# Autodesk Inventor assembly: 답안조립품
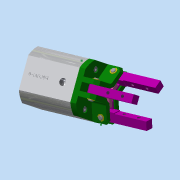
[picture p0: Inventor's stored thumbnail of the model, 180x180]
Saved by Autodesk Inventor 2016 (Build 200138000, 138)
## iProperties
Created: 2020-02
Part Number: 답안조립품
Document SubType Name: Assembly
Designer: MIRAE
Author: MIRAE
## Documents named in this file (11)
- C:\Users\MIRAE\Desktop\700206V1026\답안조립품.iam
- C:\Users\MIRAE\Desktop\700206V1026\본체.ipt
- C:\Users\MIRAE\Desktop\700206V1026\본체헤드.ipt
- C:\Users\MIRAE\Desktop\700206V1026\로드.ipt
- C:\Users\MIRAE\Desktop\700206V1026\핑거.ipt
- C:\Users\MIRAE\Desktop\700206V1026\핀 A.ipt
- C:\Users\MIRAE\Desktop\700206V1026\E링.ipt
- C:\Users\MIRAE\Desktop\700206V1026\볼트 M4.ipt
- C:\Users\MIRAE\Desktop\700206V1026\피스톤.ipt
- C:\Users\MIRAE\Desktop\700206V1026\O-RING 34x40.ipt
- C:\Users\MIRAE\Desktop\700206V1026\O-RING 12x16.ipt
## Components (16 placed, 6 different names)
1. 핑거:3
2. 핑거:4
3. 핑거:5
4. 핀 A:1
5. E링:1
6. E링:2
7. 핀 A:2
8. E링:3
9. E링:4
10. 핀 A:3
11. E링:5
12. E링:6
13. 피스톤:1
14. O-RING 12x16:1
15. O-RING 34x40:2
16. O-RING 34x40:3
## Named parameters: d13_d11 = 0, d14_d12 = 0, d15_d11 = 0, d16_d12 = 0
